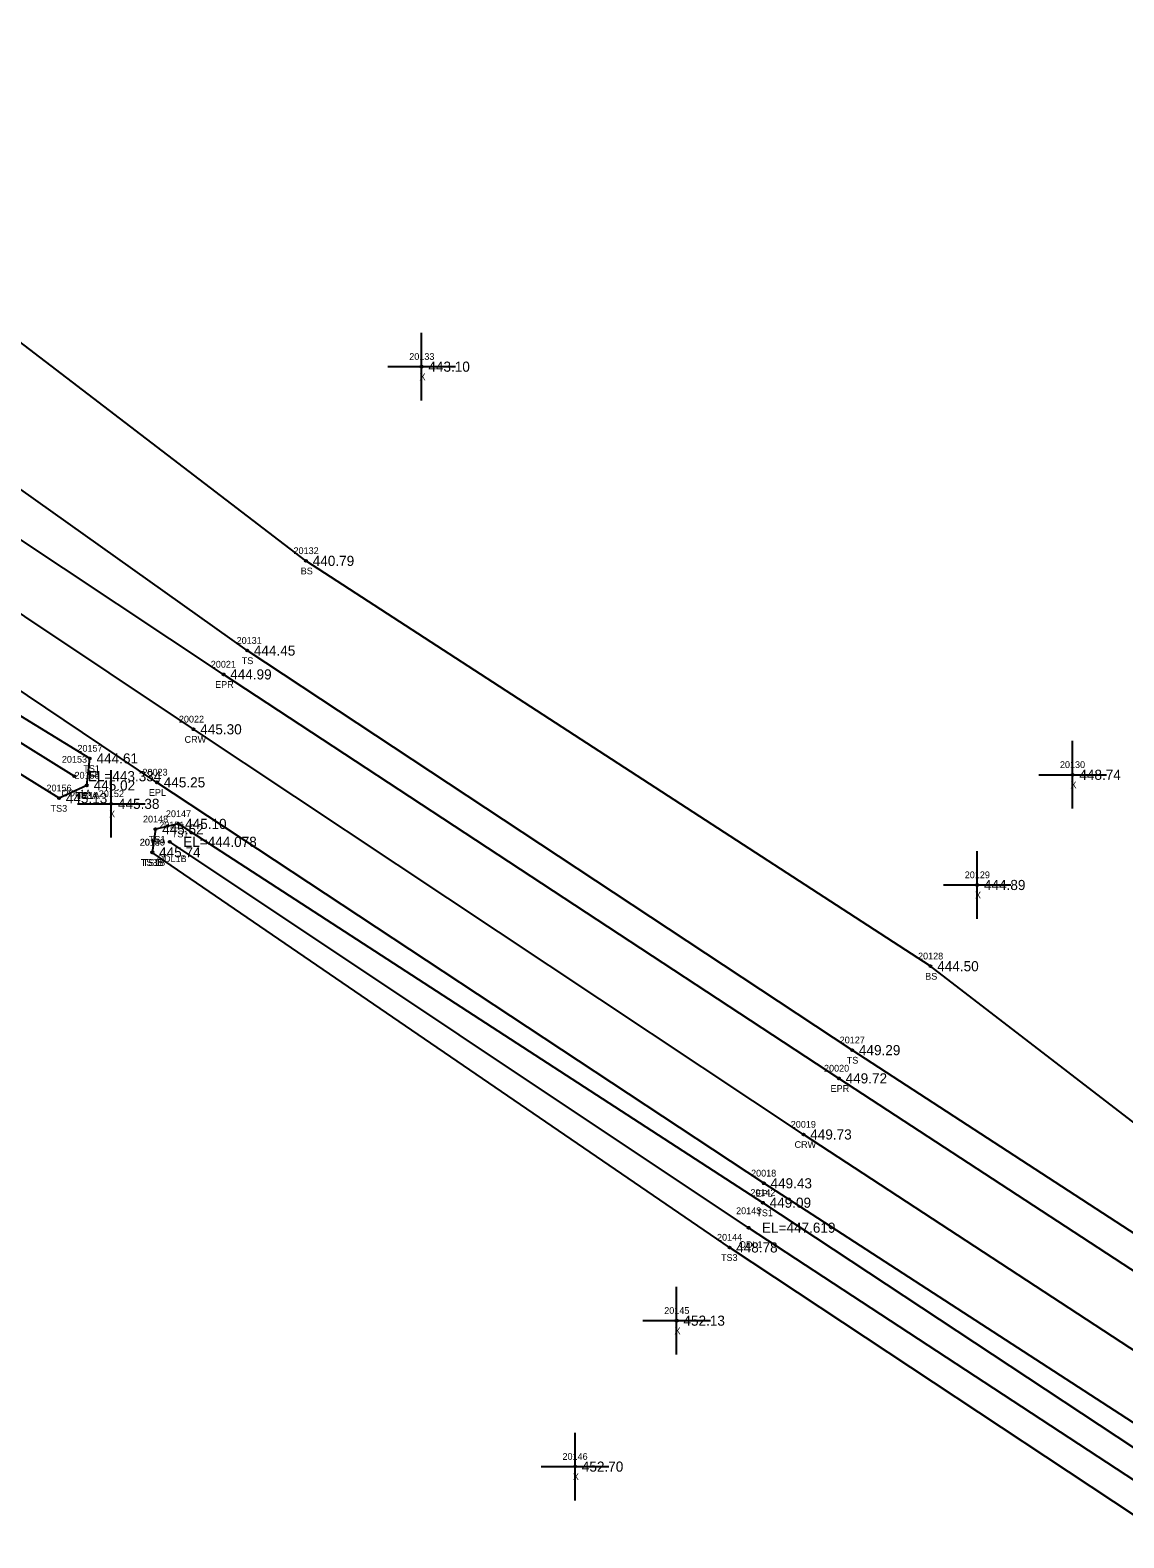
# Model space of a CAD drawing. Extents: x 1797709 to 1799052, y 896018 to 896955.
# Drawn here: x 1798544.9 to 1798706.7, y 896239.9 to 896463 of the extents above; entities that cross this region are included whole.
import ezdxf

# ---------------------------------------------------------------- set-up
doc = ezdxf.new("R2010")
doc.units = 0
for name, color, linetype in [('RD_DTM_BkLn1', 7, 'Continuous'), ('RD_DTM_BkLn2', 7, 'Continuous'), ('RD_DTM_BkLn_txCode', 7, 'Continuous'), ('RD_EX_H2O', 7, 'Continuous'), ('RD_EX_H2O_txCode', 7, 'Continuous'), ('RD_EX_Misc', 7, 'Continuous'), ('RD_EX_Misc_txCode', 7, 'Continuous'), ('RD_EX_Road', 7, 'Continuous'), ('RD_EX_Road_txCode', 7, 'Continuous'), ('RD_EX_TX_H2O_ELEV', 7, 'Continuous'), ('RD_EX_TX_Misc_ELEV', 7, 'Continuous'), ('RD_EX_TX_Road_ELEV', 7, 'Continuous'), ('RD_HC_Survey_ELEV', 7, 'Continuous'), ('RD_HC_Survey_txCode', 7, 'Continuous'), ('RD_SMD_Locator', 7, 'Continuous')]:
    doc.layers.add(name, color=color, linetype=linetype)

msp = doc.modelspace()

# ---------------------------------------------------------------- linework, layer by layer
at = {"layer": 'RD_DTM_BkLn1'}
msp.add_lwpolyline([(1799011.08, 896069.91), (1798925.85, 896126.62), (1798837.59, 896184.3), (1798748.15, 896241.48), (1798659.28, 896299.6), (1798569.04, 896359.56), (1798481.49, 896418.06), (1798400.67, 896472.53)], dxfattribs=at)
at = {"layer": 'RD_DTM_BkLn2'}
for points in [[(1798779.67, 896245.03), (1798759.32, 896261.95), (1798678.07, 896324.5), (1798585.68, 896384.49), (1798503.1, 896447.71), (1798419.26, 896491.43), (1798406.44, 896491.18)], [(1799018.13, 896081.6), (1798933.54, 896137.5), (1798843.36, 896196.36), (1798754.6, 896254.77), (1798666.48, 896312.08), (1798576.97, 896371.21), (1798490.12, 896433.01), (1798431.99, 896471.79), (1798411.1, 896485.73), (1798407.22, 896483.62)], [(1798553.27, 896351.26), (1798553.7, 896355.25), (1798471.73, 896405.52), (1798397.85, 896454.42), (1798392.33, 896458.86), (1798393.06, 896462.1)], [(1798553.27, 896351.26), (1798549.15, 896349.36), (1798468.15, 896399.67), (1798427.49, 896425.24)], [(1798795.25, 896192.62), (1798794.86, 896196.46), (1798739.65, 896232.38), (1798653.27, 896289.5), (1798566.8, 896345.56), (1798563.4, 896344.77), (1798562.95, 896341.35)], [(1798795.25, 896192.62), (1798791.74, 896189.71), (1798735.36, 896225.26), (1798648.32, 896282.88), (1798562.95, 896341.35)]]:
    msp.add_lwpolyline(points, dxfattribs=at)
at = {"layer": 'RD_EX_H2O'}
for points in [[(1798551.41, 896352.62), (1798470.44, 896403.02), (1798427.49, 896425.24)], [(1798793.78, 896193.66), (1798737.76, 896229.05), (1798651.14, 896285.8), (1798565.52, 896342.9)]]:
    msp.add_lwpolyline(points, dxfattribs=at)
at = {"layer": 'RD_EX_Misc'}
for p, q in [((1798602.79, 896408.23), (1798602.79, 896418.23)), ((1798597.79, 896413.23), (1798607.79, 896413.23)), ((1798699.1, 896347.83), (1798699.1, 896357.83)), ((1798556.87, 896343.53), (1798556.87, 896353.53)), ((1798694.1, 896352.83), (1798704.1, 896352.83)), ((1798551.87, 896348.53), (1798561.87, 896348.53)), ((1798684.98, 896331.52), (1798684.98, 896341.52)), ((1798679.98, 896336.52), (1798689.98, 896336.52)), ((1798640.52, 896267.04), (1798640.52, 896277.04)), ((1798635.52, 896272.04), (1798645.52, 896272.04)), ((1798625.49, 896245.44), (1798625.49, 896255.44)), ((1798620.49, 896250.44), (1798630.49, 896250.44))]:
    msp.add_line(p, q, dxfattribs=at)
at = {"layer": 'RD_EX_Road'}
for points in [[(1799016.83, 896078.37), (1798931.94, 896134.3), (1798843.73, 896191.67), (1798753.3, 896249.87), (1798664.51, 896307.9), (1798573.47, 896367.69), (1798486.82, 896425.22), (1798405.79, 896479.79), (1798400.67, 896472.53)], [(1799005.77, 896063.27), (1798987.67, 896075.09), (1798974.89, 896083.47), (1798920.67, 896119.42), (1798834.47, 896175.11), (1798832.16, 896176.64), (1798822.63, 896182.83), (1798742.86, 896234.39), (1798653.4, 896292.37), (1798563.64, 896351.71), (1798476.02, 896410.61), (1798395.49, 896463.92), (1798400.67, 896472.53)]]:
    msp.add_lwpolyline(points, dxfattribs=at)
at = {"layer": 'RD_SMD_Locator'}
for centre in [(1798602.79, 896413.23), (1798585.68, 896384.49), (1798576.97, 896371.21), (1798573.47, 896367.69), (1798569.04, 896359.56), (1798553.7, 896355.25), (1798551.41, 896352.62), (1798699.1, 896352.83), (1798553.27, 896351.26), (1798553.27, 896351.26), (1798563.64, 896351.71), (1798549.15, 896349.36), (1798556.87, 896348.53), (1798563.4, 896344.77), (1798566.8, 896345.56), (1798562.95, 896341.35), (1798562.95, 896341.35), (1798565.52, 896342.9), (1798684.98, 896336.52), (1798678.07, 896324.5), (1798666.48, 896312.08), (1798664.51, 896307.9), (1798659.28, 896299.6), (1798653.4, 896292.37), (1798653.27, 896289.5), (1798651.14, 896285.8), (1798648.32, 896282.88), (1798640.52, 896272.04), (1798625.49, 896250.44)]:
    msp.add_circle(centre, 0.15, dxfattribs=at)

# ---------------------------------------------------------------- texts
at = {"layer": 'RD_DTM_BkLn_txCode'}
for s, p in [('20132', (1798583.84, 896385.49)), ('BS', (1798584.9, 896382.49)), ('20131', (1798575.42, 896372.21)), ('TS', (1798576.18, 896369.21)), ('20157', (1798551.87, 896356.25)), ('20154', (1798551.44, 896352.26)), ('20155', (1798551.44, 896352.26)), ('TS1', (1798552.74, 896353.25)), ('20156', (1798547.29, 896350.36)), ('TS3A', (1798551.54, 896349.26)), ('TS1A', (1798551.82, 896349.26)), ('TS3', (1798547.9, 896347.36)), ('20148', (1798561.57, 896345.77)), ('20147', (1798564.96, 896346.56)), ('TS1', (1798562.44, 896342.77)), ('TS1', (1798565.84, 896343.56)), ('20150', (1798561.08, 896342.35)), ('20149', (1798561.12, 896342.35)), ('TS3B', (1798561.23, 896339.35)), ('TS1B', (1798561.52, 896339.35)), ('20128', (1798676.23, 896325.5)), ('BS', (1798677.29, 896322.5)), ('20127', (1798664.64, 896313.08)), ('TS', (1798665.68, 896310.08)), ('20142', (1798651.43, 896290.5)), ('TS1', (1798652.31, 896287.5)), ('20144', (1798646.49, 896283.88)), ('TS3', (1798647.08, 896280.88))]:
    msp.add_text(s, height=1, dxfattribs=at).set_placement(p)
at = {"layer": 'RD_EX_H2O_txCode'}
for s, p in [('20153', (1798549.57, 896354.62)), ('ODL1A', (1798549.51, 896349.62)), ('20151', (1798563.97, 896344.9)), ('ODL1B', (1798563.64, 896339.9)), ('20143', (1798649.31, 896287.8)), ('ODL1', (1798649.73, 896282.8))]:
    msp.add_text(s, height=1, dxfattribs=at).set_placement(p)
at = {"layer": 'RD_EX_Misc_txCode'}
for s, p in [('20133', (1798600.96, 896414.23)), ('X', (1798602.48, 896411.23)), ('20130', (1798697.22, 896353.83)), ('20152', (1798555.03, 896349.53)), ('X', (1798698.78, 896350.83)), ('X', (1798556.55, 896346.53)), ('20129', (1798683.14, 896337.52)), ('X', (1798684.66, 896334.52)), ('20145', (1798638.68, 896273.04)), ('X', (1798640.2, 896270.04)), ('20146', (1798623.63, 896251.44)), ('X', (1798625.17, 896248.44))]:
    msp.add_text(s, height=1, dxfattribs=at).set_placement(p)
at = {"layer": 'RD_EX_Road_txCode'}
for s, p in [('20021', (1798571.6, 896368.69)), ('EPR', (1798572.24, 896365.69)), ('20023', (1798561.49, 896352.71)), ('EPL', (1798562.44, 896349.71)), ('20020', (1798662.32, 896308.9)), ('EPR', (1798663.29, 896305.9)), ('20018', (1798651.53, 896293.37)), ('EPL', (1798652.2, 896290.37))]:
    msp.add_text(s, height=1, dxfattribs=at).set_placement(p)
at = {"layer": 'RD_EX_TX_H2O_ELEV'}
for s, p in [('EL=443.334', (1798553.41, 896351.87)), ('EL=444.078', (1798567.52, 896342.15)), ('EL=447.619', (1798653.14, 896285.05))]:
    msp.add_text(s, height=1.5, dxfattribs=at).set_placement(p)
at = {"layer": 'RD_EX_TX_Misc_ELEV'}
for s, p in [('443.10', (1798603.79, 896412.48)), ('440.79', (1798586.68, 896383.74)), ('444.45', (1798577.97, 896370.46)), ('444.61', (1798554.7, 896354.5)), ('448.74', (1798700.1, 896352.08)), ('445.02', (1798554.27, 896350.51)), ('445.02', (1798554.27, 896350.51)), ('445.13', (1798550.15, 896348.61)), ('445.38', (1798557.87, 896347.78)), ('445.10', (1798567.8, 896344.81)), ('445.52', (1798564.4, 896344.02)), ('445.74', (1798563.95, 896340.6)), ('445.74', (1798563.95, 896340.6)), ('444.89', (1798685.98, 896335.77)), ('444.50', (1798679.07, 896323.75)), ('449.29', (1798667.48, 896311.33)), ('449.09', (1798654.27, 896288.75)), ('448.78', (1798649.32, 896282.13)), ('452.13', (1798641.52, 896271.29)), ('452.70', (1798626.49, 896249.69))]:
    msp.add_text(s, height=1.5, dxfattribs=at).set_placement(p)
at = {"layer": 'RD_EX_TX_Road_ELEV'}
for s, p in [('444.99', (1798574.47, 896366.94)), ('445.25', (1798564.64, 896350.96)), ('449.72', (1798665.51, 896307.15)), ('449.43', (1798654.4, 896291.62))]:
    msp.add_text(s, height=1.5, dxfattribs=at).set_placement(p)
at = {"layer": 'RD_HC_Survey_ELEV'}
for s, p in [('445.30', (1798570.04, 896358.81)), ('449.73', (1798660.28, 896298.85))]:
    msp.add_text(s, height=1.5, dxfattribs=at).set_placement(p)
at = {"layer": 'RD_HC_Survey_txCode'}
for s, p in [('20022', (1798566.88, 896360.56)), ('CRW', (1798567.72, 896357.56)), ('20019', (1798657.4, 896300.6)), ('CRW', (1798657.96, 896297.6))]:
    msp.add_text(s, height=1, dxfattribs=at).set_placement(p)

doc.saveas('drawing.dxf')
